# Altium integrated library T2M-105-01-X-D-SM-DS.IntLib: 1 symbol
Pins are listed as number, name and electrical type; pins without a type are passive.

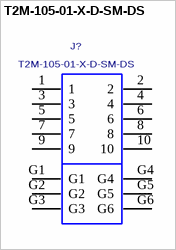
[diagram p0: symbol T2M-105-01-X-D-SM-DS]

## T2M-105-01-X-D-SM-DS
designator J?
2mm Shrouded TerminaL Strip, 10 Pins, Dual Screw Down.; MANUFACTURER: SAMTEC
footprint T2M-105-01-X-D-SM-DS
pins: 1, 2, 3, 4, 5, 6, 7, 8, 9, 10, G1, G2, G3, G4, G5, G6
